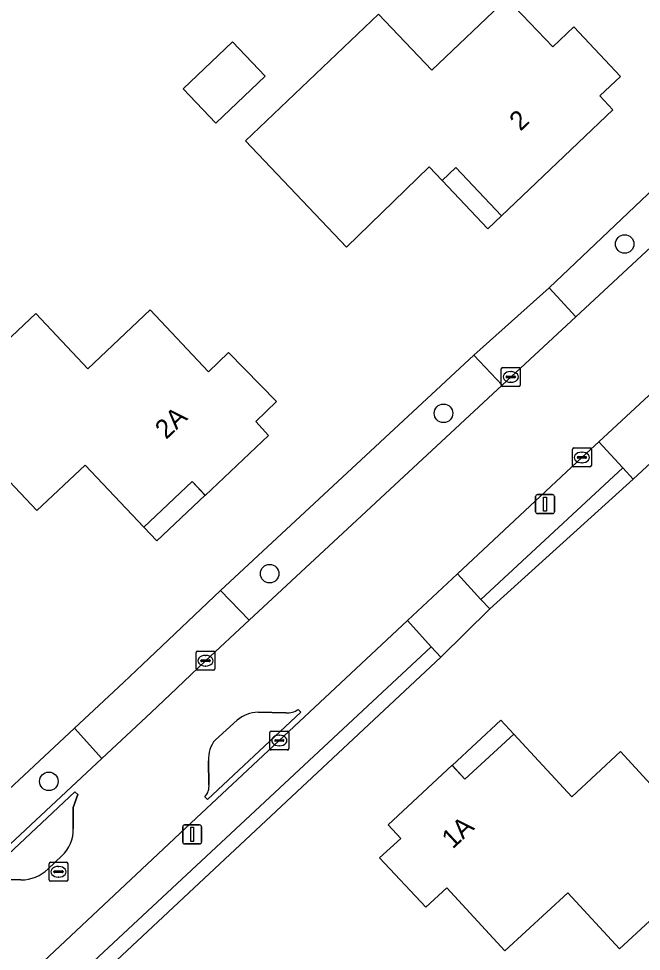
# Model space of a CAD drawing. Extents: x 162661 to 163484, y 380247 to 381230.
# Drawn here: x 163366.19 to 163399.03, y 380884.6 to 380933.79 of the extents above; entities that cross this region are included whole.
import ezdxf

# ---------------------------------------------------------------- set-up
doc = ezdxf.new("R2010")
doc.units = 0
for name, color, linetype in [('IMGEO_Boom', 7, 'Continuous'), ('IMGEO_Erf', 7, 'Continuous'), ('IMGEO_Groenvoorziening', 7, 'Continuous'), ('IMGEO_Haag', 7, 'Continuous'), ('IMGEO_Kolk', 7, 'Continuous'), ('IMGEO_Lichtmast', 7, 'Continuous'), ('IMGEO_Pand', 7, 'Continuous'), ('IMGEO_Pand_nummerreeks', 7, 'Continuous'), ('IMGEO_Pand_overbouw', 7, 'Continuous'), ('IMGEO_Parkeervlak_halfverhard', 7, 'Continuous'), ('IMGEO_Rijbaan_lokaal_gesloten', 7, 'Continuous'), ('IMGEO_Rioolput', 7, 'Continuous'), ('IMGEO_Voetpad_open', 7, 'Continuous')]:
    doc.layers.add(name, color=color, linetype=linetype)

msp = doc.modelspace()

# ---------------------------------------------------------------- linework, layer by layer
at = {"layer": 'IMGEO_Boom'}
for centre in [(163398.156, 380921.903), (163388.6, 380912.973), (163379.429, 380904.517), (163367.785, 380893.566)]:
    msp.add_circle(centre, 0.489, dxfattribs=at)
at = {"layer": 'IMGEO_Erf'}
for points in [[(163385.18, 380934.016), (163387.987, 380931.069), (163391.948, 380934.84), (163394.366, 380932.301), (163395.473, 380933.347), (163397.933, 380930.743), (163396.84, 380929.71), (163397.532, 380928.978), (163391.662, 380923.396), (163389.256, 380925.935), (163388.53, 380925.246), (163387.838, 380925.966), (163383.486, 380921.744), (163378.163, 380927.334)], [(163374.865, 380930.082), (163377.465, 380932.558), (163379.189, 380930.747), (163376.589, 380928.271)], [(163361.937, 380913.376), (163367.096, 380918.239), (163369.84, 380915.328), (163373.129, 380918.428), (163376.208, 380915.161), (163377.253, 380916.185), (163379.786, 380913.598), (163378.708, 380912.543), (163379.363, 380911.811), (163376.026, 380908.648), (163375.337, 380909.373), (163372.789, 380906.976), (163369.698, 380910.247), (163367.15, 380907.845)], [(163395.162, 380887.691), (163391.833, 380884.635), (163388.782, 380887.957), (163387.67, 380886.936), (163385.228, 380889.533), (163386.352, 380890.549), (163385.683, 380891.281), (163389.049, 380894.42), (163389.731, 380893.69), (163392.311, 380896.059), (163395.37, 380892.755), (163397.94, 380895.135), (163403.089, 380889.526), (163397.874, 380884.738)]]:
    msp.add_lwpolyline(points, close=True, dxfattribs=at)
for points in [[(163390.208, 380916.036), (163394.178, 380919.59), (163404.925, 380929.806), (163405.119, 380930.025)], [(163412.189, 380922.438), (163401.222, 380911.928), (163398.601, 380909.502), (163391.052, 380902.669), (163388.46, 380900.109), (163368.391, 380881.338), (163365.767, 380878.911), (163363.981, 380877.26), (163361.251, 380874.736), (163348.876, 380863.295), (163346.208, 380860.828), (163335.787, 380851.194)], [(163330.099, 380859.929), (163339.041, 380868.279), (163341.718, 380870.779), (163343.701, 380872.63), (163346.254, 380875.013), (163369.133, 380896.376), (163371.715, 380898.787), (163373.061, 380900.044), (163376.845, 380903.636), (163390.208, 380916.036)]]:
    msp.add_lwpolyline(points, dxfattribs=at)
at = {"layer": 'IMGEO_Groenvoorziening'}
for points in [[(163405.119, 380930.025), (163404.925, 380929.806), (163394.178, 380919.59), (163395.571, 380918.056), (163408.427, 380929.994), (163408.201, 380930.244), (163408.65, 380930.642), (163407.315, 380932.067), (163378.593, 380962.733)], [(163376.012, 380892.755), (163376.151, 380892.613), (163381.074, 380897.218), (163380.937, 380897.361)], [(163380.289, 380897.176), (163378.82, 380897.213)], [(163377.715, 380896.795), (163376.569, 380895.762)], [(163376.21, 380894.657), (163376.224, 380893.407)], [(163369.075, 380891.078), (163369.074, 380892.193), (163369.322, 380892.879), (163369.165, 380893.006), (163364.183, 380888.363), (163364.325, 380888.214), (163365.021, 380888.414), (163366.314, 380888.368)], [(163367.749, 380888.95), (163368.471, 380889.631)]]:
    msp.add_lwpolyline(points, dxfattribs=at)
for points in [[(163378.343, 380902.059), (163391.687, 380914.45), (163390.208, 380916.036), (163376.845, 380903.636)], [(163391.052, 380902.669), (163398.601, 380909.502), (163398.058, 380910.103), (163390.573, 380903.16)], [(163387.952, 380900.666), (163367.834, 380881.918), (163368.391, 380881.338), (163388.46, 380900.109)], [(163369.133, 380896.376), (163346.254, 380875.013), (163347.737, 380873.443), (163370.584, 380894.778)]]:
    msp.add_lwpolyline(points, close=True, dxfattribs=at)
for centre, radius, start, end in [((163378.93, 380895.253), 1.963, 93.2051, 128.2362), ((163380.356, 380898.17), 0.996, 266.1617, 305.7058), ((163377.717, 380894.778), 1.512, 139.4053, 184.5981), ((163375.475, 380893.29), 0.758, 315.1116, 8.8642), ((163367.198, 380891.012), 1.879, 312.6761, 2.0111), ((163366.309, 380890.441), 2.073, 270.1415, 314.0109)]:
    msp.add_arc(centre, radius, start, end, dxfattribs=at)
at = {"layer": 'IMGEO_Haag'}
for points in [[(163391.052, 380902.669), (163398.601, 380909.502), (163398.058, 380910.103), (163390.573, 380903.16)], [(163387.952, 380900.666), (163367.834, 380881.918), (163368.391, 380881.338), (163388.46, 380900.109)]]:
    msp.add_lwpolyline(points, close=True, dxfattribs=at)
at = {"layer": 'IMGEO_Kolk'}
for p, q in [((163391.649, 380914.466), (163391.649, 380915.318)), ((163391.724, 380915.392), (163392.576, 380915.392)), ((163392.137, 380915.172), (163392.162, 380915.172)), ((163392.65, 380915.318), (163392.65, 380914.466)), ((163391.908, 380914.886), (163391.908, 380914.898)), ((163392.346, 380914.849), (163391.948, 380914.849)), ((163391.951, 380914.935), (163392.349, 380914.935)), ((163392.16, 380914.612), (163392.135, 380914.612)), ((163392.392, 380914.898), (163392.392, 380914.886)), ((163392.576, 380914.392), (163391.724, 380914.392)), ((163395.472, 380911.145), (163396.324, 380911.145)), ((163395.397, 380910.219), (163395.397, 380911.071)), ((163395.656, 380910.639), (163395.656, 380910.651)), ((163395.699, 380910.688), (163396.097, 380910.688)), ((163395.885, 380910.925), (163395.91, 380910.925)), ((163396.14, 380910.651), (163396.14, 380910.639)), ((163396.398, 380911.071), (163396.398, 380910.219)), ((163396.094, 380910.602), (163395.696, 380910.602)), ((163395.908, 380910.365), (163395.883, 380910.365)), ((163396.324, 380910.145), (163395.472, 380910.145)), ((163375.547, 380899.502), (163375.547, 380900.354)), ((163375.622, 380900.428), (163376.474, 380900.428)), ((163376.548, 380900.354), (163376.548, 380899.502)), ((163375.806, 380899.922), (163375.806, 380899.934)), ((163376.244, 380899.885), (163375.846, 380899.885)), ((163375.849, 380899.971), (163376.247, 380899.971)), ((163376.035, 380900.208), (163376.06, 380900.208)), ((163376.29, 380899.934), (163376.29, 380899.922)), ((163376.474, 380899.428), (163375.622, 380899.428)), ((163376.058, 380899.648), (163376.033, 380899.648)), ((163379.441, 380895.294), (163379.441, 380896.146)), ((163379.516, 380896.22), (163380.368, 380896.22)), ((163379.929, 380896), (163379.954, 380896)), ((163380.442, 380896.146), (163380.442, 380895.294)), ((163379.7, 380895.714), (163379.7, 380895.726)), ((163380.138, 380895.677), (163379.74, 380895.677)), ((163379.743, 380895.763), (163380.141, 380895.763)), ((163379.952, 380895.44), (163379.927, 380895.44)), ((163380.184, 380895.726), (163380.184, 380895.714)), ((163380.368, 380895.22), (163379.516, 380895.22))]:
    msp.add_line(p, q, dxfattribs=at)
for points in [[(163391.649, 380914.466), (163391.649, 380915.318)], [(163391.724, 380915.392), (163392.576, 380915.392)], [(163392.65, 380915.318), (163392.65, 380914.466)], [(163392.576, 380914.392), (163391.724, 380914.392)], [(163395.472, 380911.145), (163396.324, 380911.145)], [(163395.397, 380910.219), (163395.397, 380911.071)], [(163396.398, 380911.071), (163396.398, 380910.219)], [(163396.324, 380910.145), (163395.472, 380910.145)], [(163375.547, 380899.502), (163375.547, 380900.354)], [(163375.622, 380900.428), (163376.474, 380900.428)], [(163376.548, 380900.354), (163376.548, 380899.502)], [(163376.474, 380899.428), (163375.622, 380899.428)], [(163379.441, 380895.294), (163379.441, 380896.146)], [(163379.516, 380896.22), (163380.368, 380896.22)], [(163380.442, 380896.146), (163380.442, 380895.294)], [(163380.368, 380895.22), (163379.516, 380895.22)]]:
    msp.add_lwpolyline(points, dxfattribs=at)
for centre, radius, start, end in [((163391.726, 380915.316), 0.0765, 91.552, 178.448), ((163391.726, 380915.316), 0.0765, 91.552, 178.448), ((163392.574, 380915.316), 0.0765, 1.552, 88.448), ((163392.574, 380915.316), 0.0765, 1.552, 88.448), ((163391.948, 380914.895), 0.0403, 85.8775, 175.7526), ((163391.945, 380914.885), 0.0366, 178.938, 274.7102), ((163392.349, 380914.892), 0.043, 264.8664, 352.4533), ((163392.353, 380914.897), 0.0386, 1.7309, 96.639), ((163391.726, 380914.468), 0.0765, 181.552, 268.448), ((163391.726, 380914.468), 0.0765, 181.552, 268.448), ((163392.574, 380914.468), 0.0765, 271.552, 358.448), ((163392.574, 380914.468), 0.0765, 271.552, 358.448), ((163395.474, 380911.069), 0.0765, 91.552, 178.448), ((163395.474, 380911.069), 0.0765, 91.552, 178.448), ((163396.322, 380911.069), 0.0765, 1.552, 88.448), ((163396.322, 380911.069), 0.0765, 1.552, 88.448), ((163395.696, 380910.648), 0.0403, 85.8775, 175.7526), ((163396.101, 380910.65), 0.0386, 1.7309, 96.639), ((163395.474, 380910.221), 0.0765, 181.552, 268.448), ((163395.474, 380910.221), 0.0765, 181.552, 268.448), ((163395.693, 380910.638), 0.0366, 178.938, 274.7102), ((163396.097, 380910.645), 0.043, 264.8664, 352.4533), ((163396.322, 380910.221), 0.0765, 271.552, 358.448), ((163396.322, 380910.221), 0.0765, 271.552, 358.448), ((163375.624, 380900.352), 0.0765, 91.552, 178.448), ((163375.624, 380900.352), 0.0765, 91.552, 178.448), ((163376.472, 380900.352), 0.0765, 1.552, 88.448), ((163376.472, 380900.352), 0.0765, 1.552, 88.448), ((163375.846, 380899.931), 0.0403, 85.8775, 175.7526), ((163375.843, 380899.921), 0.0366, 178.938, 274.7102), ((163376.247, 380899.928), 0.043, 264.8664, 352.4533), ((163376.251, 380899.933), 0.0386, 1.7309, 96.639), ((163375.624, 380899.504), 0.0765, 181.552, 268.448), ((163375.624, 380899.504), 0.0765, 181.552, 268.448), ((163376.472, 380899.504), 0.0765, 271.552, 358.448), ((163376.472, 380899.504), 0.0765, 271.552, 358.448), ((163379.518, 380896.144), 0.0765, 91.552, 178.448), ((163379.518, 380896.144), 0.0765, 91.552, 178.448), ((163380.366, 380896.144), 0.0765, 1.552, 88.448), ((163380.366, 380896.144), 0.0765, 1.552, 88.448), ((163379.74, 380895.723), 0.0403, 85.8775, 175.7526), ((163379.737, 380895.713), 0.0366, 178.938, 274.7102), ((163380.141, 380895.72), 0.043, 264.8664, 352.4533), ((163380.145, 380895.725), 0.0386, 1.7309, 96.639), ((163379.518, 380895.296), 0.0765, 181.552, 268.448), ((163379.518, 380895.296), 0.0765, 181.552, 268.448), ((163380.366, 380895.296), 0.0765, 271.552, 358.448), ((163380.366, 380895.296), 0.0765, 271.552, 358.448)]:
    msp.add_arc(centre, radius, start, end, dxfattribs=at)
for centre, major_axis, ratio, start_param, end_param in [((163392.136, 380914.892), (-0.387, 0.002), 0.722429, 4.712389, 7.853982), ((163392.161, 380914.892), (-0.39, 0.002), 0.717154, 1.570796, 4.712389), ((163395.884, 380910.645), (-0.387, 0.002), 0.722429, 4.712389, 7.853982), ((163395.909, 380910.645), (-0.39, 0.002), 0.717154, 1.570796, 4.712389), ((163376.034, 380899.928), (-0.387, 0.002), 0.722429, 4.712389, 7.853982), ((163376.059, 380899.928), (-0.39, 0.002), 0.717154, 1.570796, 4.712389), ((163379.928, 380895.72), (-0.387, 0.002), 0.722429, 4.712389, 7.853982), ((163379.953, 380895.72), (-0.39, 0.002), 0.717154, 1.570796, 4.712389)]:
    msp.add_ellipse(centre, major_axis=major_axis, ratio=ratio, start_param=start_param, end_param=end_param, dxfattribs=at)
at = {"layer": 'IMGEO_Lichtmast'}
for p, q in [((163393.558, 380908.685), (163394.348, 380908.685)), ((163394.348, 380908.685), (163393.558, 380908.685)), ((163393.458, 380907.785), (163393.458, 380908.585)), ((163393.458, 380908.585), (163393.458, 380907.785)), ((163394.448, 380908.585), (163394.448, 380907.785)), ((163394.448, 380907.785), (163394.448, 380908.585)), ((163394.348, 380907.685), (163393.558, 380907.685)), ((163393.558, 380907.685), (163394.348, 380907.685)), ((163374.849, 380890.367), (163374.849, 380891.167)), ((163374.849, 380891.167), (163374.849, 380890.367)), ((163374.949, 380891.267), (163375.739, 380891.267)), ((163375.739, 380891.267), (163374.949, 380891.267)), ((163375.839, 380891.167), (163375.839, 380890.367)), ((163375.839, 380890.367), (163375.839, 380891.167)), ((163375.739, 380890.267), (163374.949, 380890.267)), ((163374.949, 380890.267), (163375.739, 380890.267))]:
    msp.add_line(p, q, dxfattribs=at)
for points in [[(163393.878, 380908.56), (163394.028, 380908.56), (163394.028, 380907.81), (163393.878, 380907.81), (163393.878, 380908.56)], [(163375.269, 380891.142), (163375.419, 380891.142), (163375.419, 380890.392), (163375.269, 380890.392), (163375.269, 380891.142)]]:
    msp.add_lwpolyline(points, dxfattribs=at)
for centre, start, end in [((163393.558, 380908.585), 90, 180), ((163393.558, 380908.585), 90, 180), ((163394.348, 380908.585), 0, 90), ((163394.348, 380908.585), 360, 90), ((163393.558, 380907.785), 180, 270), ((163393.558, 380907.785), 180, 270), ((163394.348, 380907.785), 270, 0), ((163394.348, 380907.785), 270, 0), ((163374.949, 380891.167), 90, 180), ((163374.949, 380891.167), 90, 180), ((163375.739, 380891.167), 0, 90), ((163375.739, 380891.167), 360, 90), ((163374.949, 380890.367), 180, 270), ((163374.949, 380890.367), 180, 270), ((163375.739, 380890.367), 270, 0), ((163375.739, 380890.367), 270, 0)]:
    msp.add_arc(centre, 0.1, start, end, dxfattribs=at)
at = {"layer": 'IMGEO_Pand'}
for points in [[(163391.662, 380923.396), (163397.532, 380928.978), (163396.84, 380929.71), (163397.933, 380930.743), (163395.473, 380933.347), (163394.366, 380932.301), (163391.948, 380934.84), (163387.987, 380931.069), (163385.18, 380934.016), (163378.163, 380927.334), (163383.486, 380921.744), (163387.838, 380925.966), (163388.53, 380925.246), (163389.256, 380925.935)], [(163376.589, 380928.271), (163379.189, 380930.747), (163377.465, 380932.558), (163374.865, 380930.082)], [(163376.026, 380908.648), (163379.363, 380911.811), (163378.708, 380912.543), (163379.786, 380913.598), (163377.253, 380916.185), (163376.208, 380915.161), (163373.129, 380918.428), (163369.84, 380915.328), (163367.096, 380918.239), (163361.937, 380913.376), (163367.15, 380907.845), (163369.698, 380910.247), (163372.789, 380906.976), (163375.337, 380909.373)], [(163392.311, 380896.059), (163389.731, 380893.69), (163389.049, 380894.42), (163385.683, 380891.281), (163386.352, 380890.549), (163385.228, 380889.533), (163387.67, 380886.936), (163388.782, 380887.957), (163391.833, 380884.635), (163395.162, 380887.691), (163397.874, 380884.738), (163403.089, 380889.526), (163397.94, 380895.135), (163395.37, 380892.755)]]:
    msp.add_lwpolyline(points, close=True, dxfattribs=at)
at = {"layer": 'IMGEO_Pand_overbouw'}
for points in [[(163388.53, 380925.246), (163390.937, 380922.706), (163391.662, 380923.396), (163389.256, 380925.935)], [(163376.024, 380908.65), (163375.337, 380909.373), (163372.789, 380906.976), (163373.479, 380906.241)], [(163389.059, 380894.409), (163389.731, 380893.69), (163392.31, 380896.058), (163391.63, 380896.792)]]:
    msp.add_lwpolyline(points, close=True, dxfattribs=at)
at = {"layer": 'IMGEO_Parkeervlak_halfverhard'}
for points in [[(163398.058, 380910.103), (163396.796, 380911.477), (163395.898, 380910.645), (163389.345, 380904.515), (163390.573, 380903.16)], [(163387.952, 380900.666), (163386.701, 380902.041), (163375.559, 380891.618), (163367.502, 380884.069), (163366.621, 380883.251), (163367.834, 380881.918)]]:
    msp.add_lwpolyline(points, close=True, dxfattribs=at)
at = {"layer": 'IMGEO_Rijbaan_lokaal_gesloten'}
for points in [[(163363.968, 380880.786), (163366.621, 380883.251), (163367.502, 380884.069), (163375.559, 380891.618), (163386.701, 380902.041), (163389.345, 380904.515), (163395.898, 380910.645), (163396.796, 380911.477), (163399.424, 380913.913), (163410.47, 380924.152), (163412.305, 380925.853), (163408.427, 380929.994), (163395.571, 380918.056), (163391.687, 380914.45), (163378.343, 380902.059), (163376.048, 380899.928), (163374.534, 380898.479), (163373.189, 380897.191), (163370.584, 380894.778), (163347.737, 380873.443)], [(163380.937, 380897.361), (163381.074, 380897.218), (163376.151, 380892.613), (163376.012, 380892.755)], [(163378.82, 380897.213), (163380.289, 380897.176)], [(163376.569, 380895.762), (163377.715, 380896.795)], [(163376.224, 380893.407), (163376.21, 380894.657)], [(163366.314, 380888.368), (163365.021, 380888.414), (163364.325, 380888.214), (163364.183, 380888.363), (163369.165, 380893.006), (163369.322, 380892.879), (163369.074, 380892.193), (163369.075, 380891.078)], [(163368.471, 380889.631), (163367.749, 380888.95)]]:
    msp.add_lwpolyline(points, dxfattribs=at)
for centre, radius, start, end in [((163378.93, 380895.253), 1.963, 93.2051, 128.2362), ((163380.356, 380898.17), 0.996, 266.1617, 305.7058), ((163377.717, 380894.778), 1.512, 139.4053, 184.5981), ((163375.475, 380893.29), 0.758, 315.1116, 8.8642), ((163367.198, 380891.012), 1.879, 312.6761, 2.0111), ((163366.309, 380890.441), 2.073, 270.1415, 314.0109)]:
    msp.add_arc(centre, radius, start, end, dxfattribs=at)
at = {"layer": 'IMGEO_Rioolput'}
for p, q in [((163367.795, 380888.372), (163367.795, 380889.224)), ((163367.87, 380889.298), (163368.722, 380889.298)), ((163368.283, 380889.078), (163368.308, 380889.078)), ((163368.796, 380889.224), (163368.796, 380888.372)), ((163368.054, 380888.792), (163368.054, 380888.804)), ((163368.492, 380888.755), (163368.094, 380888.755)), ((163368.097, 380888.841), (163368.495, 380888.841)), ((163368.306, 380888.518), (163368.281, 380888.518)), ((163368.538, 380888.804), (163368.538, 380888.792)), ((163368.722, 380888.298), (163367.87, 380888.298))]:
    msp.add_line(p, q, dxfattribs=at)
for points in [[(163367.795, 380888.372), (163367.795, 380889.224)], [(163367.87, 380889.298), (163368.722, 380889.298)], [(163368.796, 380889.224), (163368.796, 380888.372)], [(163368.722, 380888.298), (163367.87, 380888.298)]]:
    msp.add_lwpolyline(points, dxfattribs=at)
for centre, radius, start, end in [((163367.872, 380889.222), 0.0765, 91.552, 178.448), ((163367.872, 380889.222), 0.0765, 91.552, 178.448), ((163368.72, 380889.222), 0.0765, 1.552, 88.448), ((163368.72, 380889.222), 0.0765, 1.552, 88.448), ((163368.094, 380888.801), 0.0403, 85.8775, 175.7526), ((163368.091, 380888.791), 0.0366, 178.938, 274.7102), ((163368.495, 380888.798), 0.043, 264.8664, 352.4533), ((163368.499, 380888.803), 0.0386, 1.7309, 96.639), ((163367.872, 380888.374), 0.0765, 181.552, 268.448), ((163367.872, 380888.374), 0.0765, 181.552, 268.448), ((163368.72, 380888.374), 0.0765, 271.552, 358.448), ((163368.72, 380888.374), 0.0765, 271.552, 358.448)]:
    msp.add_arc(centre, radius, start, end, dxfattribs=at)
for centre, major_axis, ratio, start_param, end_param in [((163368.282, 380888.798), (-0.387, 0.002), 0.722429, 4.712389, 7.853982), ((163368.307, 380888.798), (-0.39, 0.002), 0.717154, 1.570796, 4.712389)]:
    msp.add_ellipse(centre, major_axis=major_axis, ratio=ratio, start_param=start_param, end_param=end_param, dxfattribs=at)
at = {"layer": 'IMGEO_Voetpad_open'}
for points in [[(163395.571, 380918.056), (163394.178, 380919.59), (163390.208, 380916.036), (163391.687, 380914.45)], [(163399.424, 380913.913), (163396.796, 380911.477), (163398.058, 380910.103), (163398.601, 380909.502), (163401.222, 380911.928), (163400.67, 380912.577)], [(163387.952, 380900.666), (163388.46, 380900.109), (163391.052, 380902.669), (163390.573, 380903.16), (163389.345, 380904.515), (163386.701, 380902.041)], [(163378.343, 380902.059), (163376.845, 380903.636), (163373.061, 380900.044), (163371.715, 380898.787), (163369.133, 380896.376), (163370.584, 380894.778), (163373.189, 380897.191), (163374.534, 380898.479), (163376.048, 380899.928)]]:
    msp.add_lwpolyline(points, close=True, dxfattribs=at)

# ---------------------------------------------------------------- texts
at = {"layer": 'IMGEO_Pand_nummerreeks'}
for s, rotation, p in [('2', 43.5607, (163392.659, 380927.821)), ('2A', 43.4208, (163373.971, 380911.564)), ('1A', 43.0114, (163389.082, 380889.966))]:
    msp.add_text(s, height=1, rotation=rotation, dxfattribs=at).set_placement(p)

doc.saveas('drawing.dxf')
